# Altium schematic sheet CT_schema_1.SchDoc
size 627 x 548 mm
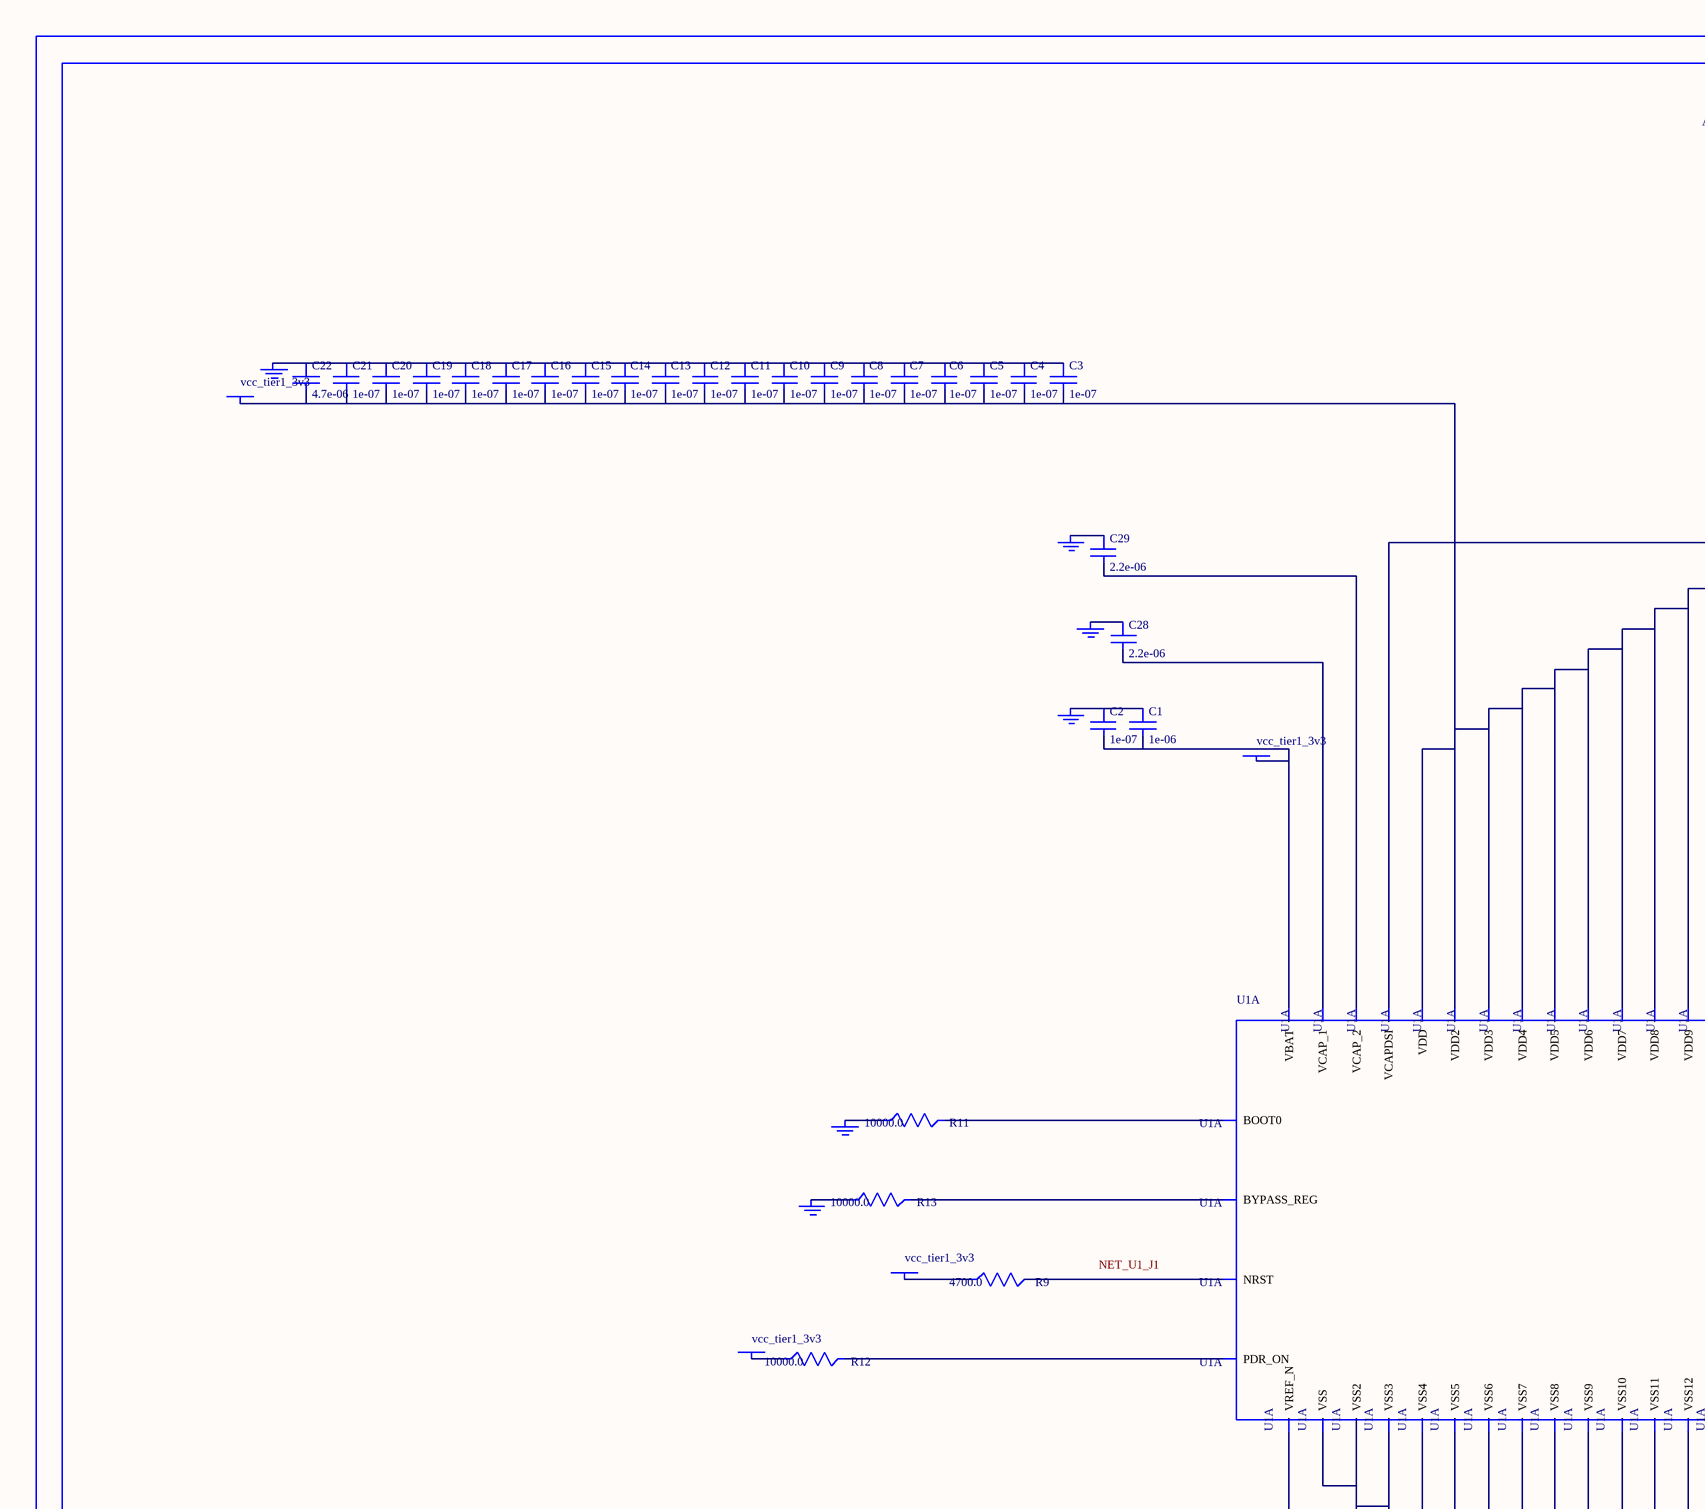
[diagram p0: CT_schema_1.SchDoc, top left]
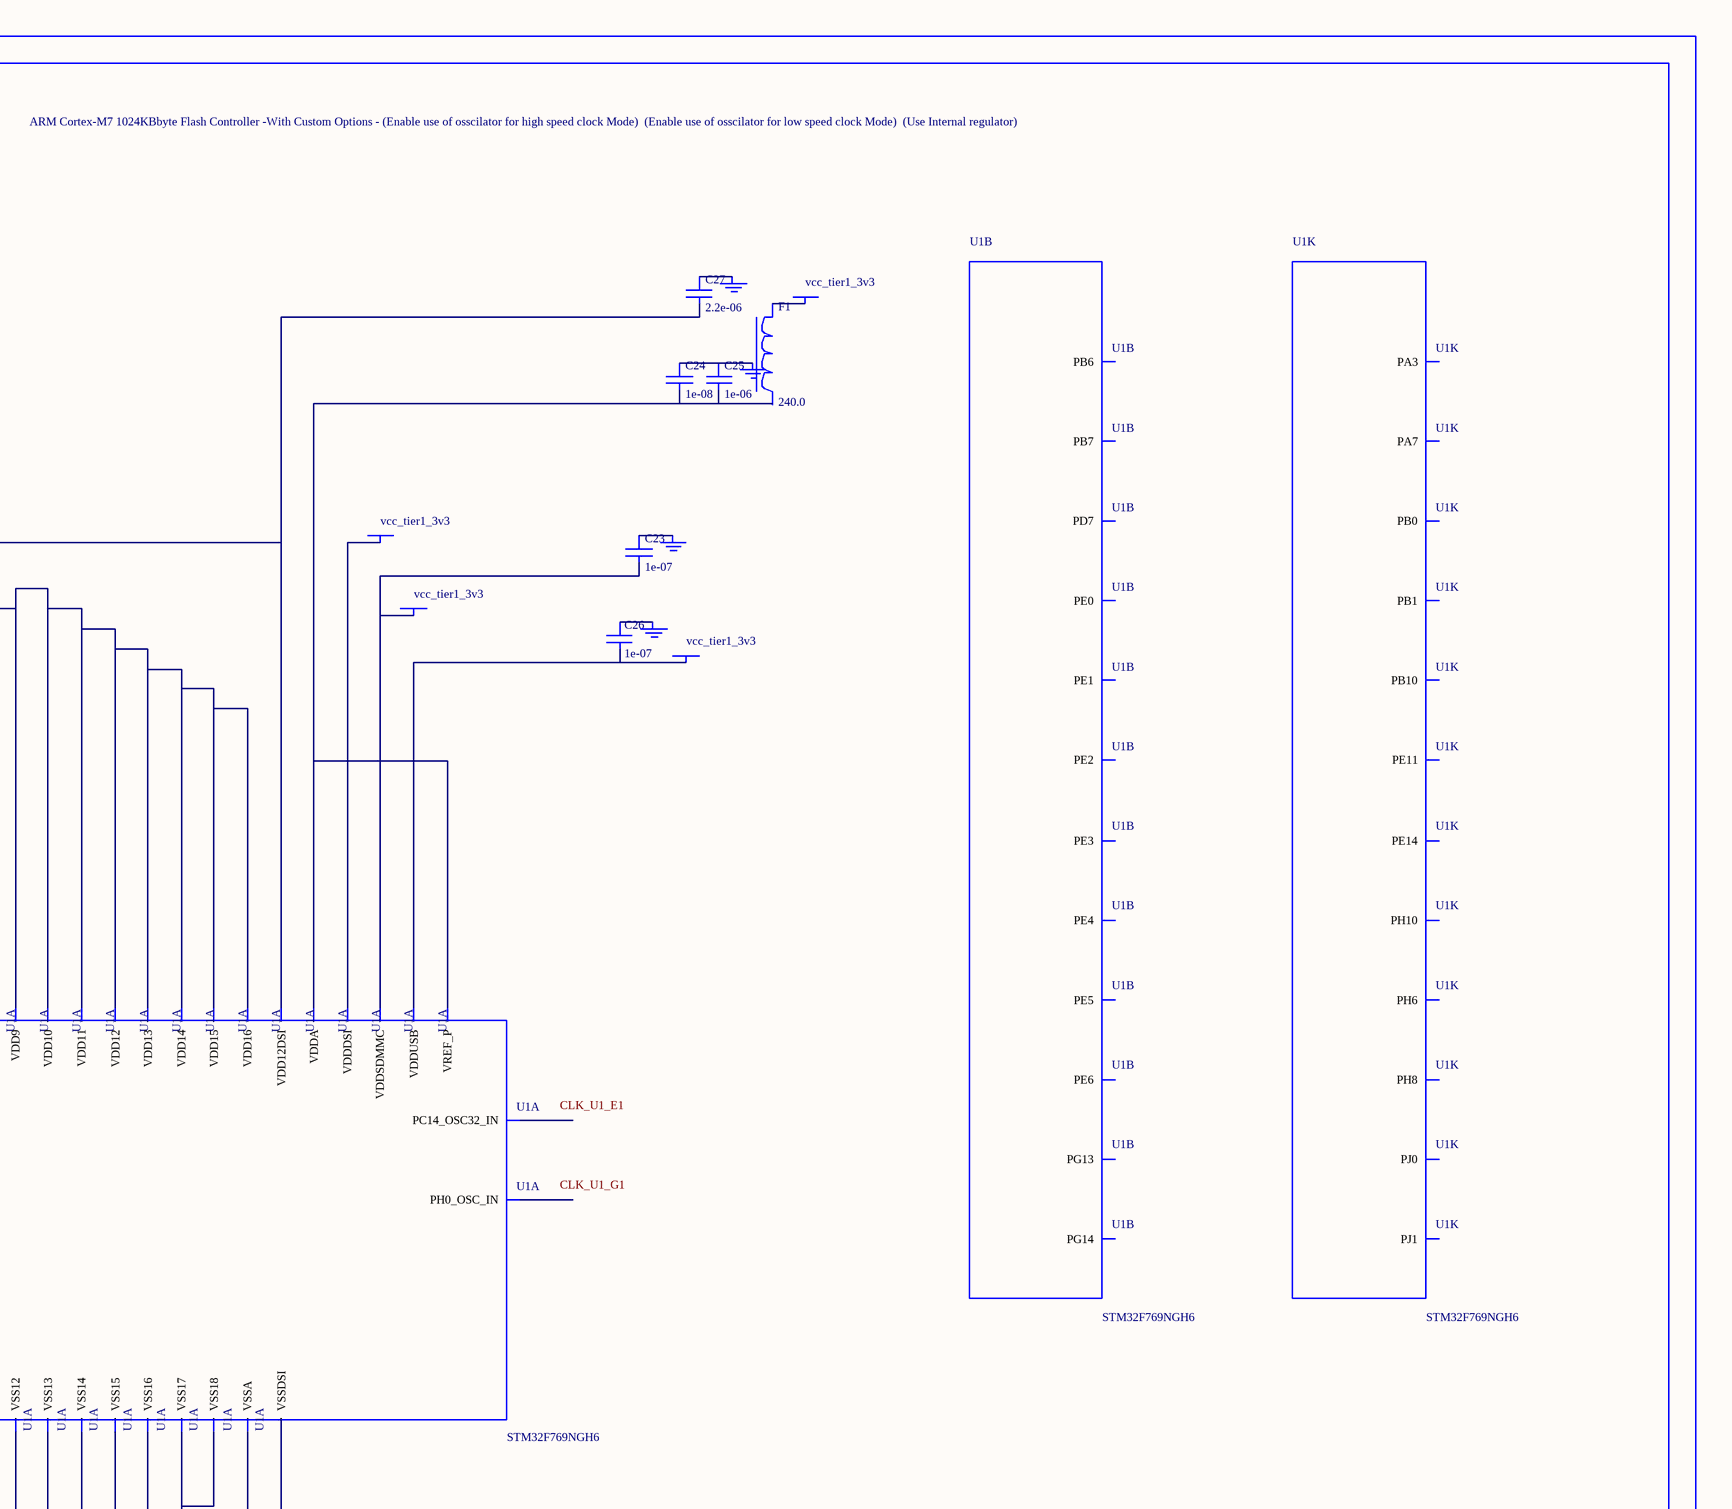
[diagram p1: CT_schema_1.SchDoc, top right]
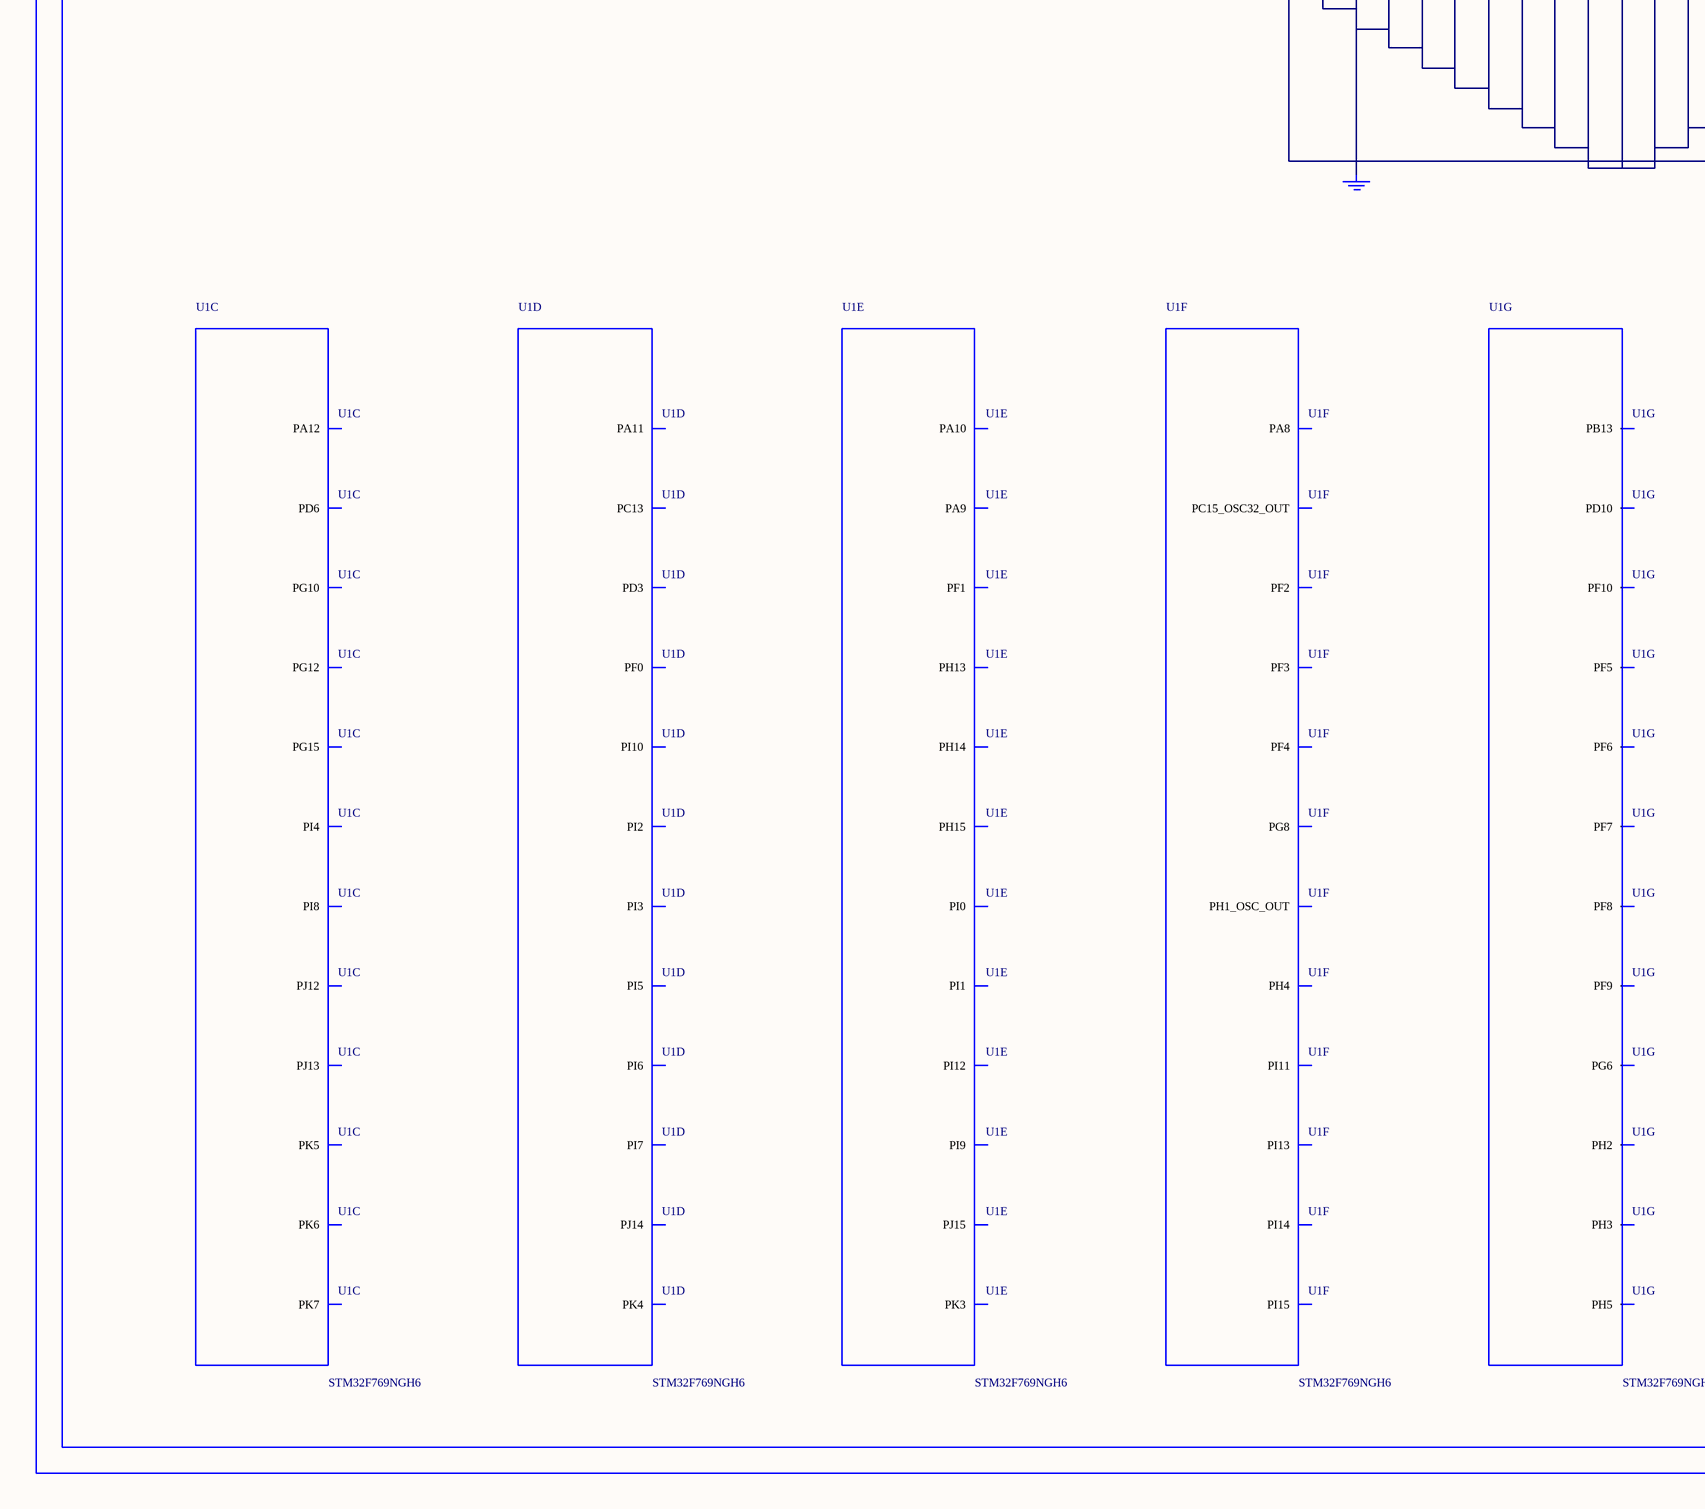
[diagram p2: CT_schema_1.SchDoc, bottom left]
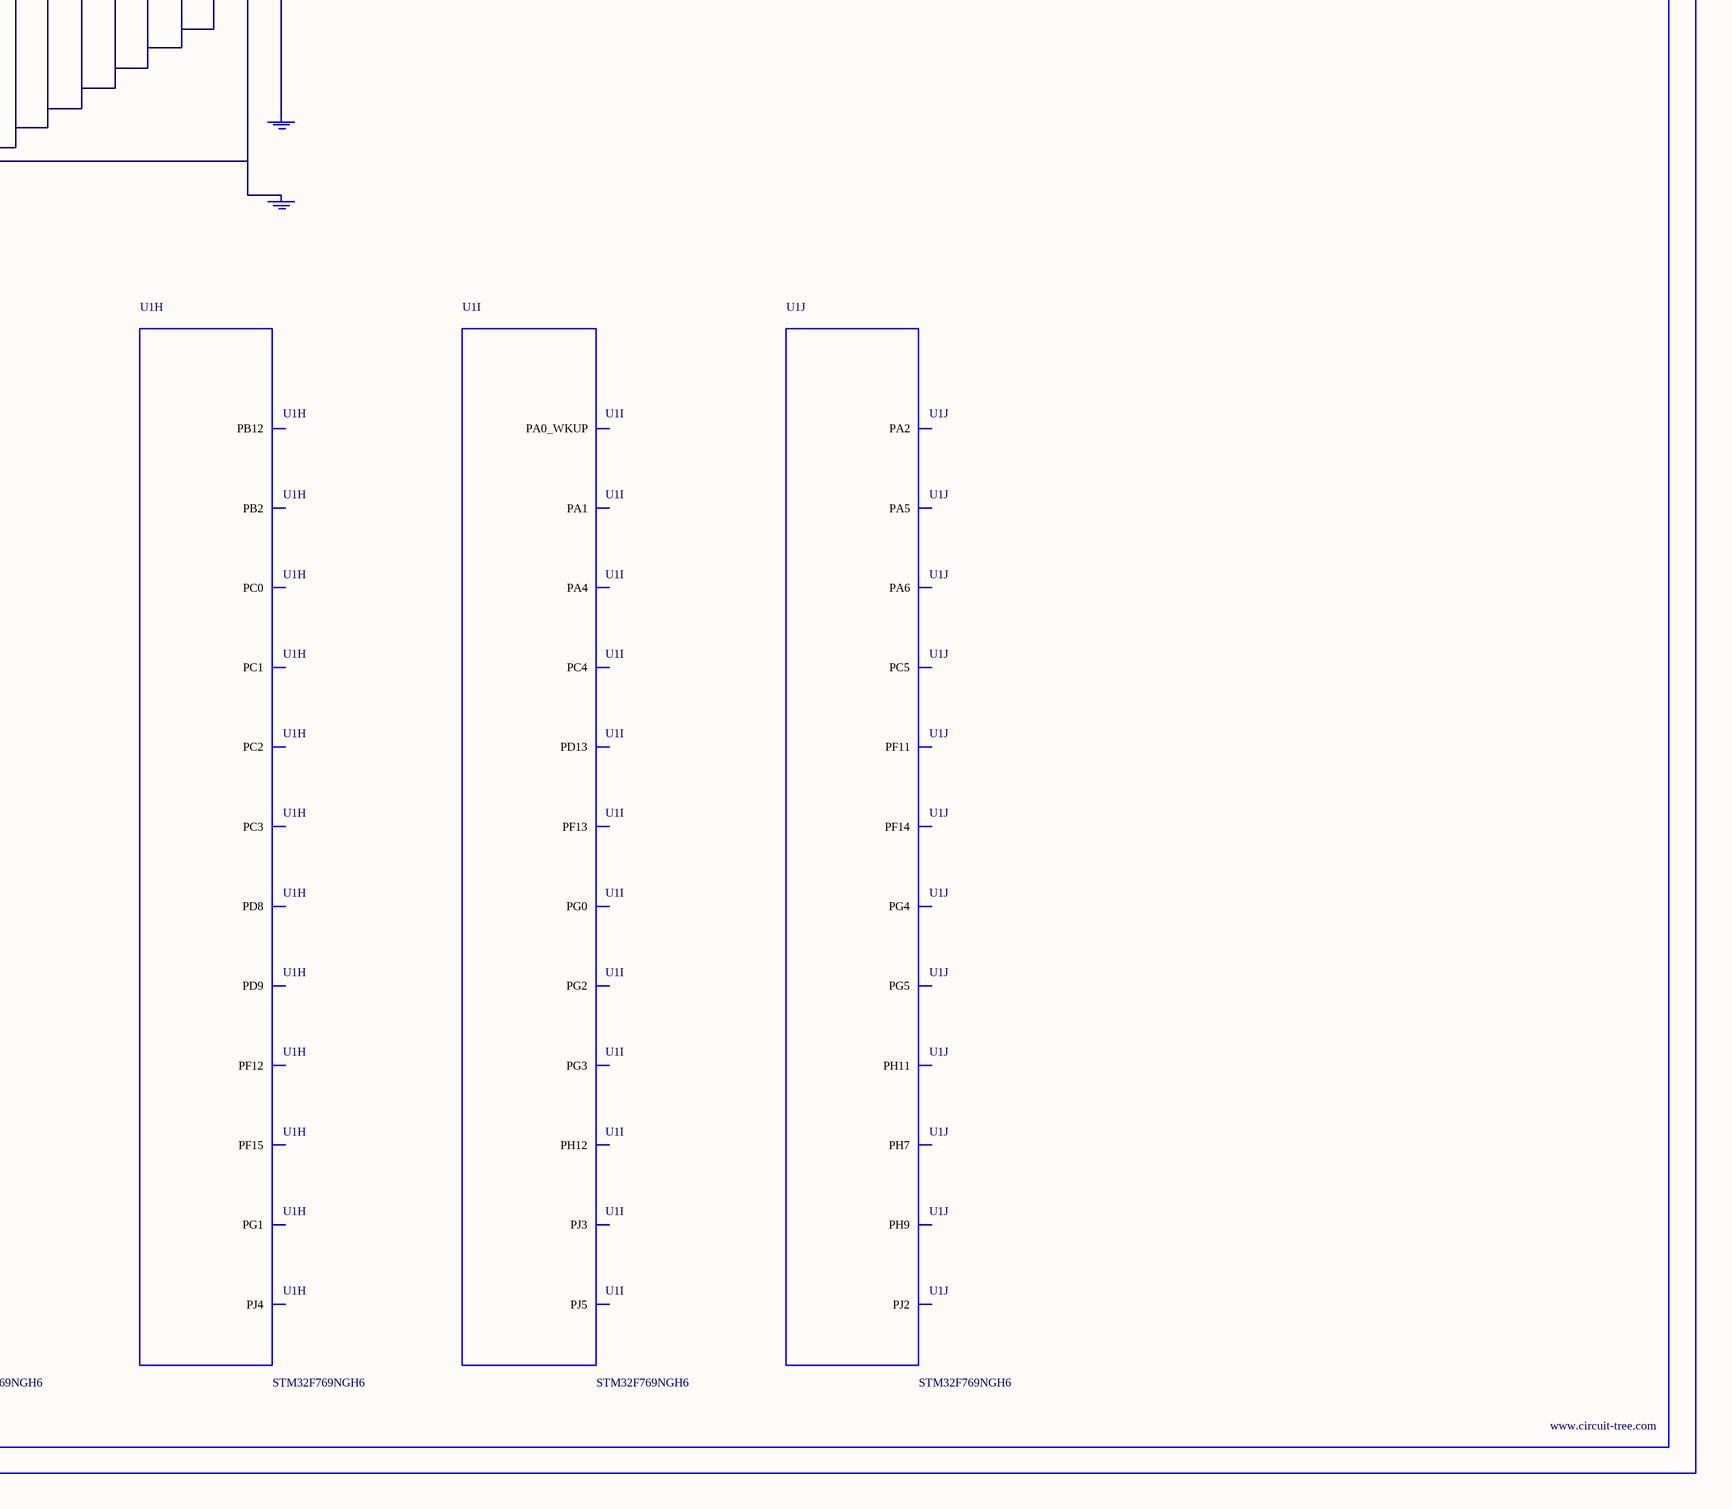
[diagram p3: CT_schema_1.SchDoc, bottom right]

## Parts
BORDER0  (no value)
C1  1e-06  [C0603]
C2  1e-07  [C0603]
C3  1e-07  [C0603]
C4  1e-07  [C0603]
C5  1e-07  [C0603]
C6  1e-07  [C0603]
C7  1e-07  [C0603]
C8  1e-07  [C0603]
C9  1e-07  [C0603]
C10  1e-07  [C0603]
C11  1e-07  [C0603]
C12  1e-07  [C0603]
C13  1e-07  [C0603]
C14  1e-07  [C0603]
C15  1e-07  [C0603]
C16  1e-07  [C0603]
C17  1e-07  [C0603]
C18  1e-07  [C0603]
C19  1e-07  [C0603]
C20  1e-07  [C0603]
C21  1e-07  [C0603]
C22  4.7e-06  [C0603]
C23  1e-07  [C0603]
C24  1e-08  [C0603]
C25  1e-06  [C0603]
C26  1e-07  [C0603]
C27  2.2e-06  [C0603]
C28  2.2e-06  [C0603]
C29  2.2e-06  [C0603]
F1  240.0  [L0603]
GND_INSTANCE_0_0  (no value)
GND_INSTANCE_0_1  (no value)
GND_INSTANCE_0_2  (no value)
GND_INSTANCE_0_3  (no value)
GND_INSTANCE_0_4  (no value)
GND_INSTANCE_0_5  (no value)
GND_INSTANCE_0_6  (no value)
GND_INSTANCE_0_7  (no value)
GND_INSTANCE_0_8  (no value)
GND_INSTANCE_0_9  (no value)
GND_INSTANCE_0_10  (no value)
GND_INSTANCE_0_11  (no value)
GND_INSTANCE_0_12  (no value)
POWER_INSTANCE_0_0  vcc_tier1_3v3
POWER_INSTANCE_0_1  vcc_tier1_3v3
POWER_INSTANCE_0_2  vcc_tier1_3v3
POWER_INSTANCE_0_3  vcc_tier1_3v3
POWER_INSTANCE_0_4  vcc_tier1_3v3
POWER_INSTANCE_0_5  vcc_tier1_3v3
POWER_INSTANCE_0_6  vcc_tier1_3v3
POWER_INSTANCE_0_7  vcc_tier1_3v3
R9  4700.0  [R0603]
R11  10000.0  [R0603]
R12  10000.0  [R0603]
R13  10000.0  [R0603]
U1  STM32F769NGH6  [TFBGA216]  (parts A,B,C,D,E,F,G,H,I,J,K of 17)

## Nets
NetC1_1: C1.1 C2.1 GND_INSTANCE_0_0.0(GND)
NetC1_2: C1.2 C2.2 POWER_INSTANCE_0_0.0(PWR) U1.C1(VBAT)
NetC3_1: C3.1 C4.1 C5.1 C6.1 C7.1 C8.1 C9.1 C10.1 C11.1 C12.1 C13.1 C14.1 C15.1 C16.1 C17.1 C18.1 C19.1 C20.1 C21.1 C22.1 GND_INSTANCE_0_2.0(GND)
NetC3_2: C3.2 C4.2 C5.2 C6.2 C7.2 C8.2 C9.2 C10.2 C11.2 C12.2 C13.2 C14.2 C15.2 C16.2 C17.2 C18.2 C19.2 C20.2 C21.2 C22.2 POWER_INSTANCE_0_2.0(PWR) U1.E7(VDD2) U1.E8(VDD3) U1.E10(VDD) U1.F4(VDD5) U1.F5(VDD6) U1.F11(VDD4) U1.G5(VDD7) U1.H5(VDD8) U1.J5(VDD10) U1.J11(VDD9) U1.K5(VDD12) U1.K11(VDD11) U1.L7(VDD14) U1.L8(VDD15) U1.L9(VDD16) U1.L10(VDD13)
NetC23_1: C23.1 GND_INSTANCE_0_4.0(GND)
NetC23_2: C23.2 POWER_INSTANCE_0_3.0(PWR) U1.E9(VDDSDMMC)
NetC24_1: C24.1 C25.1 GND_INSTANCE_0_1.0(GND)
NetC24_2: C24.2 C25.2 U1.P1(VREF_P) U1.R1(VDDA)
NetC26_1: C26.1 GND_INSTANCE_0_5.0(GND)
NetC26_2: C26.2 POWER_INSTANCE_0_5.0(PWR) U1.G11(VDDUSB)
NetC27_1: C27.1 GND_INSTANCE_0_6.0(GND)
NetC27_2: C27.2 U1.G13(VDD12DSI) U1.K12(VCAPDSI)
NetC28_1: C28.1 GND_INSTANCE_0_8.0(GND)
NetC28_2: C28.2 U1.L11(VCAP_1)
NetC29_1: C29.1 GND_INSTANCE_0_9.0(GND)
NetC29_2: C29.2 U1.E11(VCAP_2)
NetF1_1: F1.1 POWER_INSTANCE_0_1.0(PWR)
NetGND_INSTANCE_0_3_0: GND_INSTANCE_0_3.0(GND) R11.1
NetGND_INSTANCE_0_7_0: GND_INSTANCE_0_7.0(GND) R13.1
NetGND_INSTANCE_0_10_0: GND_INSTANCE_0_10.0(GND) U1.M1(VSSA) U1.N1(VREF_N)
NetGND_INSTANCE_0_11_0: GND_INSTANCE_0_11.0(GND) U1.F2(VSS2) U1.F6(VSS3) U1.F7(VSS4) U1.F8(VSS5) U1.F9(VSS6) U1.F10(VSS) U1.G6(VSS8) U1.G10(VSS7) U1.H6(VSS10) U1.H10(VSS9) U1.J6(VSS12) U1.J10(VSS11) U1.K6(VSS14) U1.K7(VSS15) U1.K8(VSS16) U1.K9(VSS17) U1.K10(VSS13) U1.L6(VSS18)
NetGND_INSTANCE_0_12_0: GND_INSTANCE_0_12.0(GND) U1.G12(VSSDSI)
NetPOWER_INSTANCE_0_4_0: POWER_INSTANCE_0_4.0(PWR) R12.1
NetPOWER_INSTANCE_0_6_0: POWER_INSTANCE_0_6.0(PWR) U1.H11(VDDDSI)
NetPOWER_INSTANCE_0_7_0: POWER_INSTANCE_0_7.0(PWR) R9.1
NetR9_2: R9.2 U1.J1(NRST)
NetR11_2: R11.2 U1.E6(BOOT0)
NetR12_2: R12.2 U1.E5(PDR_ON)
NetR13_2: R13.2 U1.L5(BYPASS_REG)

Not connected (* = marked no-connect by the designer): F1 2; U1 A1(PE4) A2(PE3) A3(PE2) A4(PG14) A5(PE1) A6(PE0) A11(PD7) B1(PE5) B2(PE6) B3(PG13) B5(PB7) B6(PB6) B7(PG15) B9(PJ13) B10(PJ12) B11(PD6) B15(PA12) C2(PI8) C3(PI4) C4(PK7) C5(PK6) C6(PK5) C7(PG12) C8(PG10) C9(PJ14) C11(PD3) C13(PI3) C14(PI2) C15(PA11) D1(PC13) D2(PF0) D3(PI5) D4(PI7) D5(PI10) D6(PI6) D7(PK4) D8(PK3) D10(PJ15) D13(PH15) D14(PI1) D15(PA10) E1(PC14_OSC32_IN) E2(PF1) E3(PI12) E4(PI9) E12(PH13) E13(PH14) E14(PI0) E15(PA9) F1(PC15_OSC32_OUT) F3(PI11) F15(PA8) G1(PH0_OSC_IN) G2(PF2) G3(PI13) G4(PI15) H1(PH1_OSC_OUT) H2(PF3) H3(PI14) H4(PH4) H14(PG8) J2(PF4) J3(PH5) J4(PH3) J15(PG6) K1(PF7) K2(PF6) K3(PF5) K4(PH2) K14(PB13) K15(PD10) L1(PF10) L2(PF9) L3(PF8) L4(PC3) L13(PB12) L14(PD9) L15(PD8) M2(PC0) M3(PC1) M4(PC2) M5(PB2) M6(PF12) M7(PG1) M8(PF15) M9(PJ4) M11(PD13) M12(PG3) M13(PG2) M14(PJ5) M15(PH12) N2(PA1) N3(PA0_WKUP) N4(PA4) N5(PC4) N6(PF13) N7(PG0) N8(PJ3) N11(PG5) N12(PG4) N13(PH7) N14(PH9) N15(PH11) P2(PA2) P3(PA6) P4(PA5) P5(PC5) P6(PF14) P7(PJ2) P8(PF11) P10(PE11) P11(PE14) P12(PB10) P13(PH6) P14(PH8) P15(PH10) R2(PA3) R3(PA7) R4(PB1) R5(PB0) R6(PJ0) R7(PJ1)

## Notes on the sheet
- Labels drawn without touching a wire or pin: CLK_U1_E1, CLK_U1_G1, NET_U1_J1

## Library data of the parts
BORDER0 = BORDER_PAGE0
C1 C25 = C0603C105K3RACTU
C2-C21 C23 C26 = 06035C104K4Z2A
C22 = GRM188R6YA475KE15D
C24 = 06035C103K4Z2A
C27-C29 = C0603C225K8RACTU
F1 = Z0603C241ASMST
GND_INSTANCE_0_0-GND_INSTANCE_0_12 = GND
POWER_INSTANCE_0_0-POWER_INSTANCE_0_7 = PWR
R9 = RC0603JR-074K7L
R11-R13 = RC0603JR-0710KL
